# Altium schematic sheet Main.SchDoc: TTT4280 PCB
size A3; DocumentNumber: 1; SheetNumber: 1; SheetTotal: 1; DocumentTitle: TTT4280 PCB; ProjectEngineer: Håkon Liverud
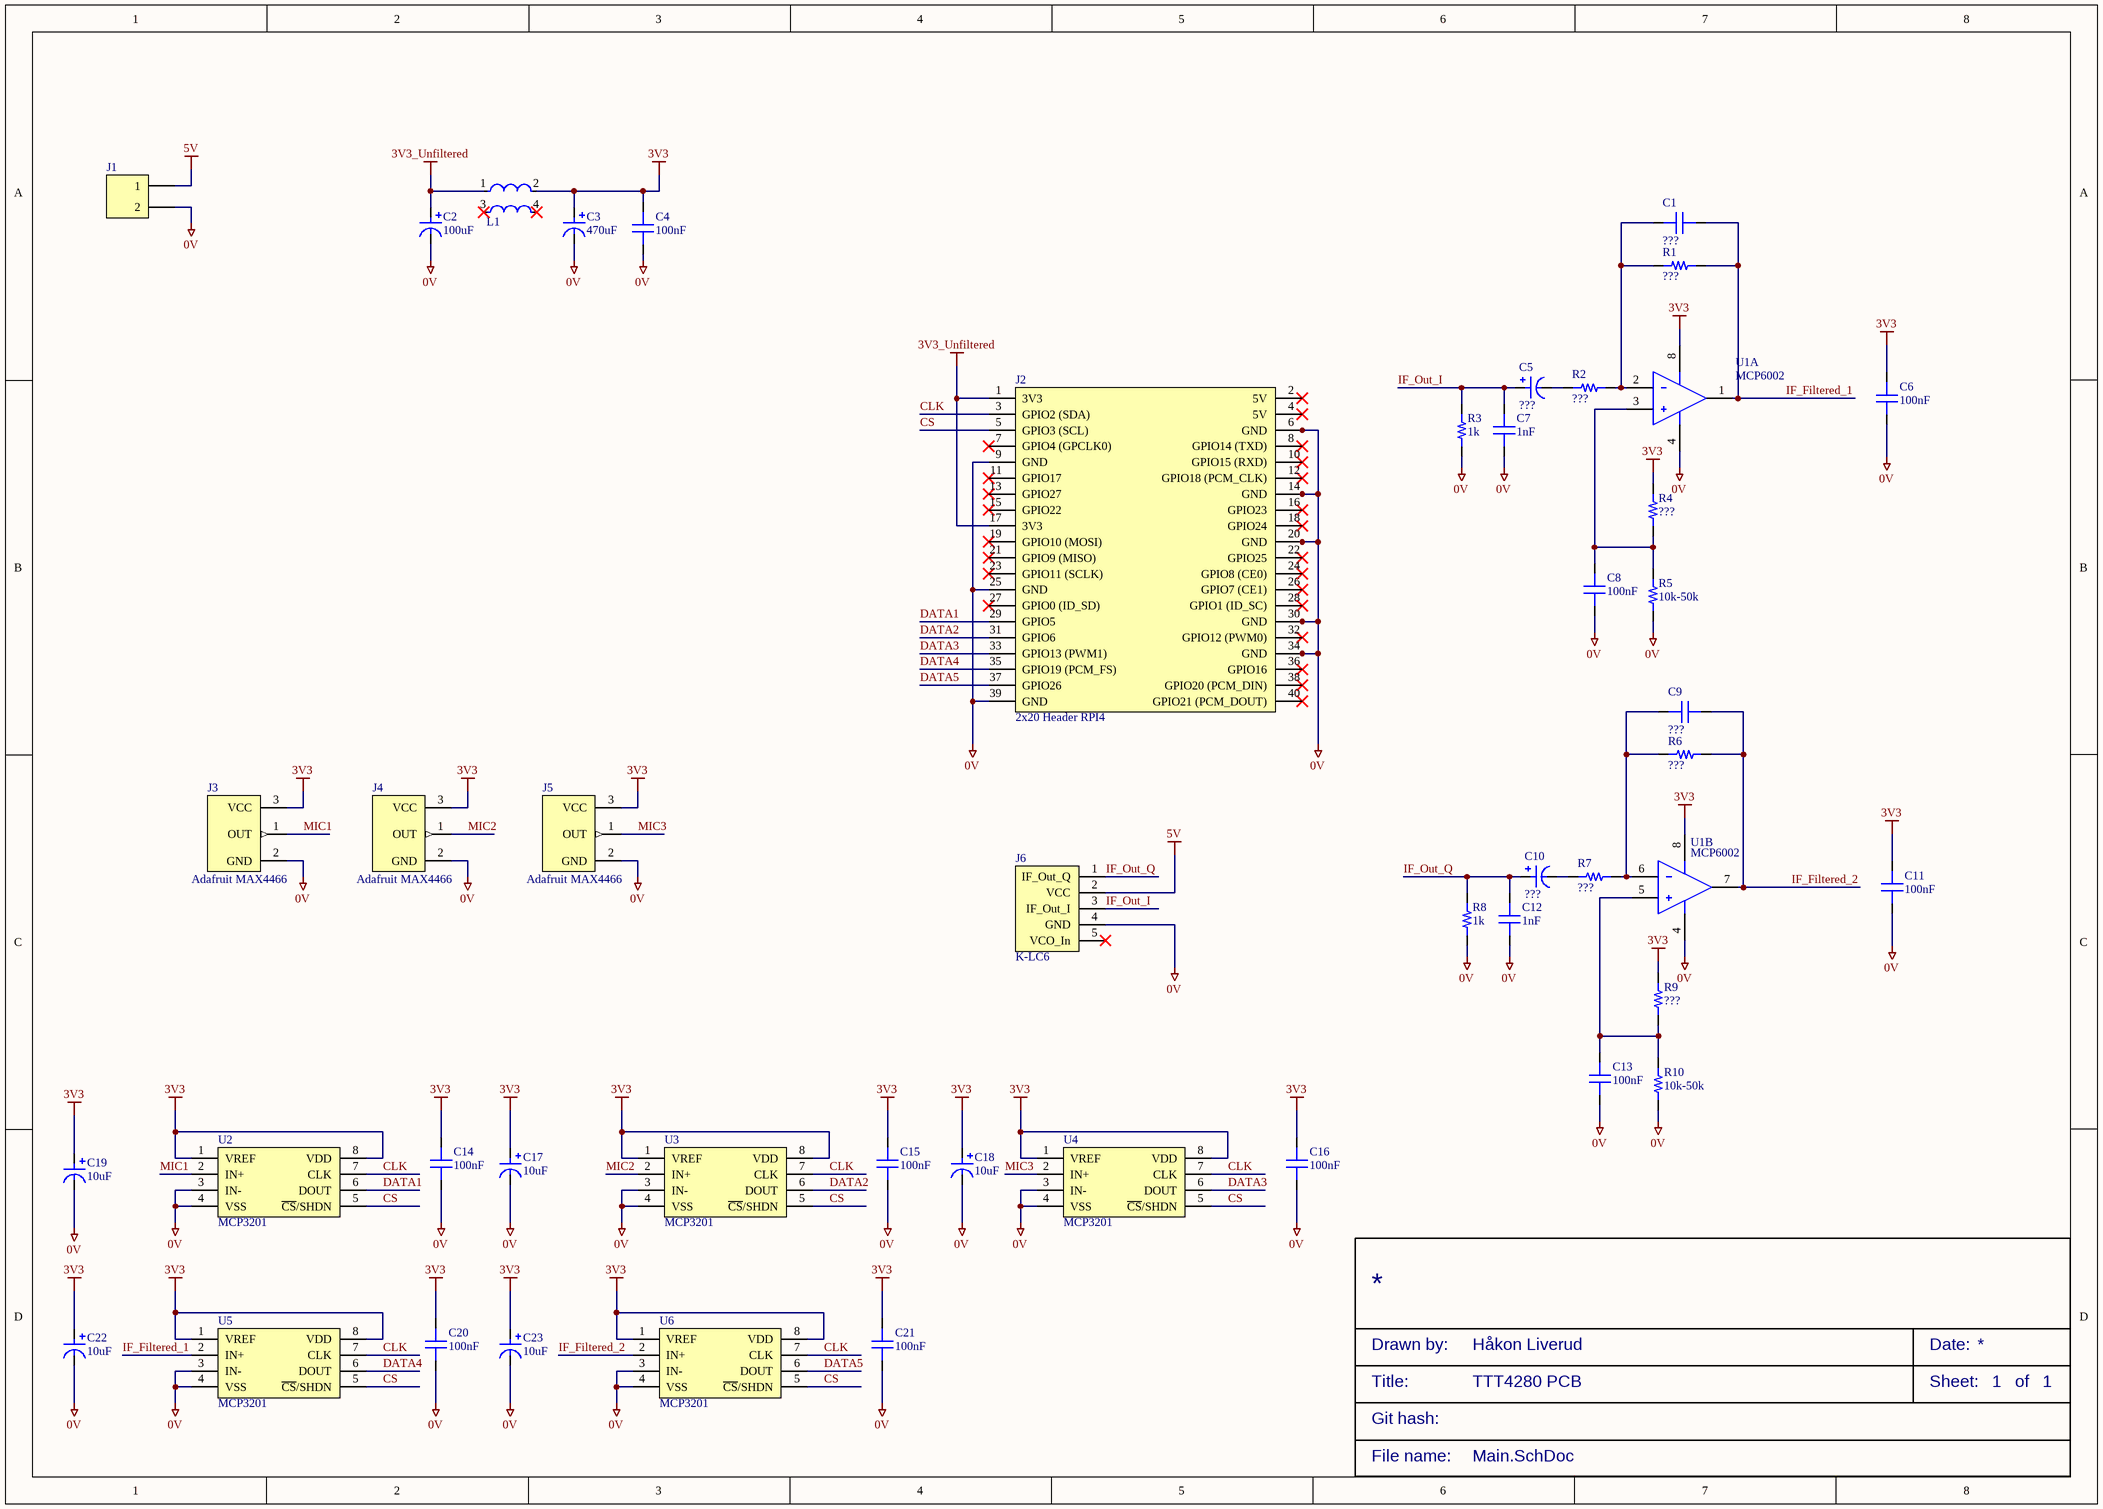
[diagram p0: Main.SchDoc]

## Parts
C1  ???  [CTHT Ceramic]
C2  100uF  [CTHT 5MM]
C3  470uF  [CTHT 8mm]
C4  100nF  [TDK Film Cap 7.3x2.5x6.5mm]
C5  ???  [CTHT 5MM]
C6  100nF  [TDK Film Cap 7.3x2.5x6.5mm]
C7  1nF  [CTHT Ceramic]
C8  100nF  [TDK Film Cap 7.3x2.5x6.5mm]
C9  ???  [CTHT Ceramic]
C10  ???  [CTHT 5MM]
C11  100nF  [TDK Film Cap 7.3x2.5x6.5mm]
C12  1nF  [CTHT Ceramic]
C13  100nF  [TDK Film Cap 7.3x2.5x6.5mm]
C14  100nF  [CTHT Ceramic]
C15  100nF  [CTHT Ceramic]
C16  100nF  [CTHT Ceramic]
C17  10uF  [CTHT 4MM]
C18  10uF  [CTHT 4MM]
C19  10uF  [CTHT 4MM]
C20  100nF  [CTHT Ceramic]
C21  100nF  [CTHT Ceramic]
C22  10uF  [CTHT 4MM]
C23  10uF  [CTHT 4MM]
J1  Header 2  [HDR1X2]  (value not drawn)
J2  2x20 Header RPI4  [HDRV40W87P254_2X20_5093X508X1067P]
J3  Adafruit MAX4466  [MODULE_1063]
J4  Adafruit MAX4466  [MODULE_1063]
J5  Adafruit MAX4466  [MODULE_1063]
J6  K-LC6  [K-LC6]
L1  100mH Inductor  [DKFP-G22G-D5J0]  (value not drawn)
R1  ???  [RTHT]
R2  ???  [RTHT]
R3  1k  [RTHT]
R4  ???  [RTHT]
R5  10k-50k  [RTHT]
R6  ???  [RTHT]
R7  ???  [RTHT]
R8  1k  [RTHT]
R9  ???  [RTHT]
R10  10k-50k  [RTHT]
U1  MCP6002  [DIP781W56P254L950H533Q8N]  (parts A,B of 2)
U2  MCP3201  [DIP781W56P254L950H533Q8N]
U3  MCP3201  [DIP781W56P254L950H533Q8N]
U4  MCP3201  [DIP781W56P254L950H533Q8N]
U5  MCP3201  [DIP781W56P254L950H533Q8N]
U6  MCP3201  [DIP781W56P254L950H533Q8N]

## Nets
0V: C2.2 C3.2 C4.1 C6.1 C7.1 C8.1 C11.1 C12.1 C13.1 C14.1 C15.1 C16.1 C17.2 C18.2 C19.2 C20.1 C21.1 C22.2 C23.2 J1.2 J2.6(GND) J2.9(GND) J2.14(GND) J2.20(GND) J2.25(GND) J2.30(GND) J2.34(GND) J2.39(GND) J3.2(GND) J4.2(GND) J5.2(GND) J6.4(GND) R3.1 R5.1 R8.1 R10.1 U1.4(VSS) U2.3(IN-) U2.4(VSS) U3.3(IN-) U3.4(VSS) U4.3(IN-) U4.4(VSS) U5.3(IN-) U5.4(VSS) U6.3(IN-) U6.4(VSS)
3V3: C3.1 C4.2 C6.2 C11.2 C14.2 C15.2 C16.2 C17.1 C18.1 C19.1 C20.2 C21.2 C22.1 C23.1 J3.3(VCC) J4.3(VCC) J5.3(VCC) L1.2 R4.2 R9.2 U1.8(VDD) U2.1(VREF) U2.8(VDD) U3.1(VREF) U3.8(VDD) U4.1(VREF) U4.8(VDD) U5.1(VREF) U5.8(VDD) U6.1(VREF) U6.8(VDD)
3V3_Unfiltered: C2.1 J2.1(3V3) J2.17(3V3) L1.1
5V: J1.1 J6.2(VCC)
CLK: J2.3(GPIO2_(SDA)) U2.7(CLK) U3.7(CLK) U4.7(CLK) U5.7(CLK) U6.7(CLK)
CS: J2.5(GPIO3_(SCL)) U2.5(~{CS}/SHDN) U3.5(~{CS}/SHDN) U4.5(~{CS}/SHDN) U5.5(~{CS}/SHDN) U6.5(~{CS}/SHDN)
DATA1: J2.29(GPIO5) U2.6(DOUT)
DATA2: J2.31(GPIO6) U3.6(DOUT)
DATA3: J2.33(GPIO13_(PWM1)) U4.6(DOUT)
DATA4: J2.35(GPIO19_(PCM_FS)) U5.6(DOUT)
DATA5: J2.37(GPIO26) U6.6(DOUT)
IF_Filtered_1: C1.2 R1.1 U1.1(VOUTA) U5.2(IN+)
IF_Filtered_2: C9.2 R6.1 U1.7(VOUTB) U6.2(IN+)
IF_Out_I: C5.1 C7.2 J6.3(IF_Out_I) R3.2
IF_Out_Q: C10.1 C12.2 J6.1(IF_Out_Q) R8.2
MIC1: J3.1(OUT) U2.2(IN+)
MIC2: J4.1(OUT) U3.2(IN+)
MIC3: J5.1(OUT) U4.2(IN+)
NetC1_1: C1.1 R1.2 R2.1 U1.2(VINA-)
NetC5_2: C5.2 R2.2
NetC8_2: C8.2 R4.1 R5.2 U1.3(VINA+)
NetC9_1: C9.1 R6.2 R7.1 U1.6(VINB-)
NetC10_2: C10.2 R7.2
NetC13_2: C13.2 R9.1 R10.2 U1.5(VINB+)

Not connected (* = marked no-connect by the designer): J2 2(5V)* 4(5V)* 7(GPIO4_(GPCLK0))* 8(GPIO14_(TXD))* 10(GPIO15_(RXD))* 11(GPIO17)* 12(GPIO18_(PCM_CLK))* 13(GPIO27)* 15(GPIO22)* 16(GPIO23)* 18(GPIO24)* 19(GPIO10_(MOSI))* 21(GPIO9_(MISO))* 22(GPIO25)* 23(GPIO11_(SCLK))* 24(GPIO8_(CE0))* 26(GPIO7_(CE1))* 27(GPIO0_(ID_SD))* 28(GPIO1_(ID_SC))* 32(GPIO12_(PWM0))* 36(GPIO16)* 38(GPIO20_(PCM_DIN))* 40(GPIO21_(PCM_DOUT))*; J6 5(VCO_In)*; L1 3* 4*

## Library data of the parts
C1 C7 C9 C12 = 1nF Ceramic: 1nF Ceramic Cap
C2 C5 C10 = 100uF 5mm THT: 100uF 5mm THT Cap
C3 = 470uF 8mm THT: 0.8pF 8mm THT Cap
C4 C6 C8 C11 C13 = 100nF Film: 100nF Film Cap; Value: 0.1uF
C14-C16 C20 C21 = 100nF Ceramic: 100nF Ceramic Cap; Value: 0.1uF
C17-C19 C22 C23 = 10uF 4mm THT: 10uF 4mm THT Cap
J1 = Header 2: Header, 2-Pin
J2 = 2222_1: GPIO MALE HEADER RASPBERRY PI
J3-J5 = 1063: Microphone Pre-Amp Audio Evaluation Board; MF: {'manufacturer': u'Adafruit'}
J6 = K-LC6: Radar Transceiver Module 24.05GHz ~ 24.25GHz Integrated, Ceramic Patch Through Hole
L1 = DKFP-G22G-D5J0: Common Mode Chokes / Filters DKFP COMP.CHOKE THT P O 0.5A 2X100mH
R1-R10 = 1k THT: 1k THT Res
U1 = MCP6022-P-8: Operational Amplifiers - Op Amps Dual 1.8V 1MHz
U2-U6 = MCP3201-BI_P: 12-Bit, 100kSPS, Single Channel ADC; Manufacturer_Name: Microchip; Manufacturer_Part_Number: MCP3201-BI/P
